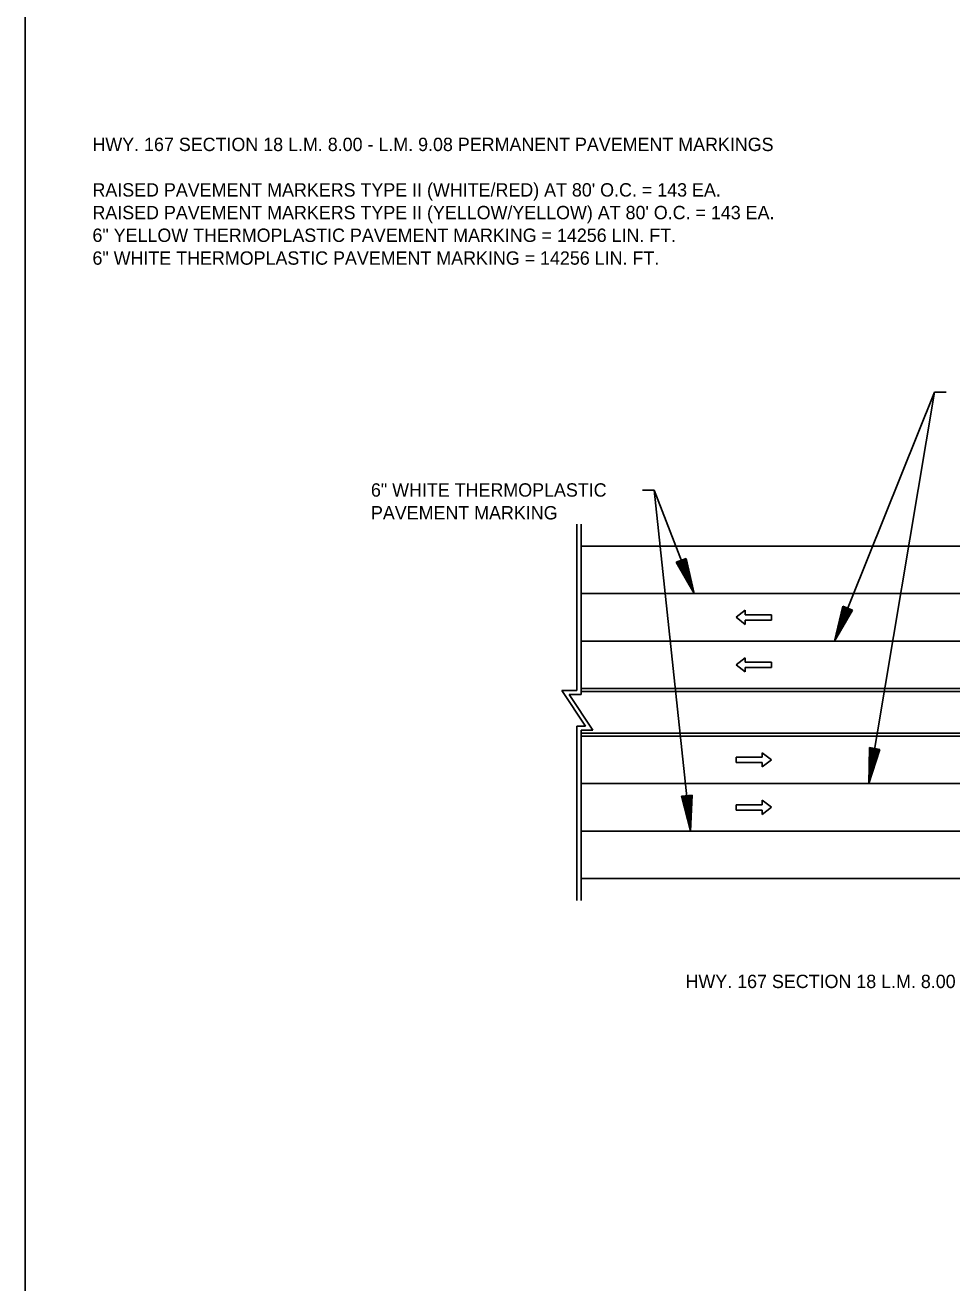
# Model space of a CAD drawing. Extents: x 1373096 to 1373266, y 381130 to 381790.
# Drawn here: x 1373096 to 1373174, y 381462.1 to 381568 of the extents above; entities that cross this region are included whole.
import ezdxf

# ---------------------------------------------------------------- set-up
doc = ezdxf.new("R2010")
doc.units = 0
for name, color, linetype in [('Default', 7, 'Continuous'), ('DSN_DRFT_Junk-No-Plot', 7, 'Continuous'), ('R_Draft', 7, 'Continuous')]:
    doc.layers.add(name, color=color, linetype=linetype)

msp = doc.modelspace()

# ---------------------------------------------------------------- linework, layer by layer
at = {"layer": 'Default'}
for p, q in [((1373172.53, 381537.08), (1373164.11, 381516.13)), ((1373172.53, 381537.08), (1373167.01, 381504.13)), ((1373173.53, 381537.08), (1373172.53, 381537.08)), ((1373147.95, 381528.85), (1373148.95, 381528.85)), ((1373148.95, 381528.85), (1373152.3, 381520.13)), ((1373148.95, 381528.85), (1373151.99, 381500.13)), ((1373142.44, 381525.96), (1373142.44, 381511.96)), ((1373142.78, 381525.96), (1373142.78, 381511.63)), ((1373151.64, 381523.09), (1373150.8, 381522.77)), ((1373150.8, 381522.77), (1373152.3, 381520.13)), ((1373150.87, 381522.79), (1373152.12, 381520.6)), ((1373150.95, 381522.82), (1373151.93, 381521.08)), ((1373151.02, 381522.85), (1373151.76, 381521.54)), ((1373151.09, 381522.88), (1373151.57, 381522.02)), ((1373151.16, 381522.9), (1373151.39, 381522.49)), ((1373151.29, 381522.95), (1373151.39, 381522.49)), ((1373151.36, 381522.98), (1373151.57, 381522.02)), ((1373151.43, 381523.01), (1373151.76, 381521.54)), ((1373151.5, 381523.04), (1373151.93, 381521.08)), ((1373151.57, 381523.06), (1373152.12, 381520.6)), ((1373151.64, 381523.09), (1373152.3, 381520.13)), ((1373156.61, 381518.73), (1373155.83, 381518.13)), ((1373156.61, 381518.73), (1373156.61, 381518.35)), ((1373156.61, 381518.35), (1373158.81, 381518.35)), ((1373158.81, 381518.35), (1373158.81, 381517.9)), ((1373164.81, 381519.08), (1373164.11, 381516.13)), ((1373165.65, 381518.74), (1373164.11, 381516.13)), ((1373164.88, 381519.05), (1373164.3, 381516.59)), ((1373165.58, 381518.77), (1373164.3, 381516.59)), ((1373164.96, 381519.02), (1373164.49, 381517.07)), ((1373165.51, 381518.8), (1373164.49, 381517.07)), ((1373165.02, 381519), (1373164.68, 381517.54)), ((1373165.44, 381518.83), (1373164.68, 381517.54)), ((1373165.65, 381518.74), (1373164.81, 381519.08)), ((1373165.1, 381518.97), (1373164.87, 381518.01)), ((1373165.37, 381518.86), (1373164.87, 381518.01)), ((1373165.17, 381518.94), (1373165.06, 381518.47)), ((1373165.3, 381518.89), (1373165.06, 381518.47)), ((1373155.83, 381518.13), (1373156.61, 381517.53)), ((1373156.61, 381517.9), (1373158.81, 381517.9)), ((1373156.61, 381517.9), (1373156.61, 381517.53)), ((1373156.61, 381514.73), (1373155.83, 381514.13)), ((1373155.83, 381514.13), (1373156.61, 381513.53)), ((1373156.61, 381514.73), (1373156.61, 381514.35)), ((1373156.61, 381514.35), (1373158.81, 381514.35)), ((1373158.81, 381514.35), (1373158.81, 381513.9)), ((1373156.61, 381513.9), (1373158.81, 381513.9)), ((1373156.61, 381513.9), (1373156.61, 381513.53)), ((1373143.16, 381508.96), (1373141.16, 381511.96)), ((1373142.44, 381511.96), (1373141.16, 381511.96)), ((1373142.78, 381511.63), (1373141.78, 381511.63)), ((1373143.78, 381508.63), (1373141.78, 381511.63)), ((1373142.44, 381508.96), (1373143.16, 381508.96)), ((1373142.44, 381494.29), (1373142.44, 381508.96)), ((1373142.78, 381494.29), (1373142.78, 381508.63)), ((1373142.78, 381508.63), (1373143.78, 381508.63)), ((1373158.04, 381506.73), (1373158.04, 381506.35)), ((1373158.04, 381506.73), (1373158.81, 381506.13)), ((1373167.06, 381507.16), (1373167.01, 381504.13)), ((1373167.95, 381507.01), (1373167.01, 381504.13)), ((1373167.95, 381507.01), (1373167.06, 381507.16)), ((1373167.14, 381507.15), (1373167.09, 381504.62)), ((1373167.88, 381507.02), (1373167.09, 381504.62)), ((1373167.21, 381507.14), (1373167.18, 381505.13)), ((1373167.8, 381507.04), (1373167.18, 381505.13)), ((1373167.29, 381507.12), (1373167.26, 381505.62)), ((1373167.73, 381507.05), (1373167.26, 381505.62)), ((1373167.36, 381507.11), (1373167.34, 381506.13)), ((1373167.65, 381507.06), (1373167.34, 381506.13)), ((1373167.44, 381507.1), (1373167.43, 381506.62)), ((1373167.58, 381507.08), (1373167.43, 381506.62)), ((1373158.04, 381506.35), (1373155.83, 381506.35)), ((1373155.83, 381506.35), (1373155.83, 381505.9)), ((1373158.04, 381505.9), (1373155.83, 381505.9)), ((1373158.81, 381506.13), (1373158.04, 381505.53)), ((1373158.04, 381505.9), (1373158.04, 381505.53)), ((1373152.13, 381503.16), (1373151.23, 381503.06)), ((1373151.23, 381503.06), (1373151.99, 381500.13)), ((1373151.31, 381503.07), (1373151.94, 381500.63)), ((1373151.38, 381503.08), (1373151.89, 381501.14)), ((1373151.46, 381503.09), (1373151.83, 381501.64)), ((1373151.53, 381503.1), (1373151.78, 381502.14)), ((1373151.61, 381503.1), (1373151.73, 381502.64)), ((1373151.75, 381503.12), (1373151.73, 381502.64)), ((1373151.82, 381503.13), (1373151.78, 381502.14)), ((1373151.9, 381503.13), (1373151.83, 381501.64)), ((1373151.98, 381503.14), (1373151.89, 381501.14)), ((1373152.05, 381503.15), (1373151.94, 381500.63)), ((1373152.13, 381503.16), (1373151.99, 381500.13)), ((1373158.04, 381502.35), (1373155.83, 381502.35)), ((1373155.83, 381502.35), (1373155.83, 381501.9)), ((1373158.04, 381502.73), (1373158.04, 381502.35)), ((1373158.04, 381502.73), (1373158.81, 381502.13)), ((1373158.04, 381501.9), (1373155.83, 381501.9)), ((1373158.81, 381502.13), (1373158.04, 381501.53)), ((1373158.04, 381501.9), (1373158.04, 381501.53))]:
    msp.add_line(p, q, dxfattribs=at)
msp.add_lwpolyline([(1373095.97, 381570.17), (1373095.97, 381460.17), (1373265.97, 381460.17), (1373265.97, 381570.17)], close=True, dxfattribs=at)
at = {"layer": 'DSN_DRFT_Junk-No-Plot'}
for points in [[(1373095.97, 381570.17), (1373265.97, 381570.17), (1373265.97, 381460.17), (1373095.97, 381460.17)], [(1373095.97, 381570.17), (1373095.97, 381460.17), (1373265.97, 381460.17), (1373265.97, 381570.17)]]:
    msp.add_lwpolyline(points, close=True, dxfattribs=at)
at = {"layer": 'R_Draft'}
for p, q in [((1373142.78, 381524.13), (1373219.17, 381524.13)), ((1373142.78, 381520.13), (1373219.17, 381520.13)), ((1373142.78, 381516.13), (1373219.17, 381516.13)), ((1373142.78, 381512.13), (1373219.17, 381512.13)), ((1373142.78, 381511.88), (1373219.17, 381511.88)), ((1373142.78, 381508.38), (1373219.17, 381508.38)), ((1373142.78, 381508.13), (1373219.17, 381508.13)), ((1373142.78, 381504.13), (1373219.17, 381504.13)), ((1373142.78, 381500.13), (1373219.17, 381500.13)), ((1373142.78, 381496.13), (1373219.17, 381496.13))]:
    msp.add_line(p, q, dxfattribs=at)

# ---------------------------------------------------------------- texts
at = {"layer": 'Default'}
for s, p in [('HWY. 167 SECTION 18 L.M. 8.00 - L.M. 9.08 PERMANENT PAVEMENT MARKINGS', (1373101.64, 381557.39)), ("RAISED PAVEMENT MARKERS TYPE II (WHITE/RED) AT 80' O.C. = 143 EA.", (1373101.64, 381553.56)), ("RAISED PAVEMENT MARKERS TYPE II (YELLOW/YELLOW) AT 80' O.C. = 143 EA.", (1373101.64, 381551.65)), ('6" YELLOW THERMOPLASTIC PAVEMENT MARKING = 14256 LIN. FT.', (1373101.64, 381549.74)), ('6" WHITE THERMOPLASTIC PAVEMENT MARKING = 14256 LIN. FT.', (1373101.64, 381547.82)), ('6" WHITE THERMOPLASTIC', (1373125.09, 381528.29)), ('PAVEMENT MARKING', (1373125.09, 381526.37))]:
    msp.add_text(s, height=1.125, dxfattribs=at).set_placement(p)
at = {"layer": 'R_Draft'}
msp.add_text('HWY. 167 SECTION 18 L.M. 8.00 - L.M. 9.08 PERMANENT PAVEMENT MARKINGS', height=1.125, dxfattribs=at).set_placement((1373151.58, 381486.91))

doc.saveas('drawing.dxf')
